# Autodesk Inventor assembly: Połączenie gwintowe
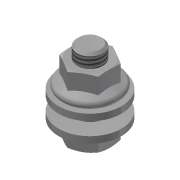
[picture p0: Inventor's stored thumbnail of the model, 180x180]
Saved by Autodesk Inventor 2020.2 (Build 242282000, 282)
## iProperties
Manager: www.cadconsulting.pl
Company: Fabian Stasiak CAD Consulting
ClientObjectVersion: 1
Created: 2011-01
Part Number: Połączenie gwintowe
Document SubType Name: Assembly
Designer: F.Stasiak
Author: F.Stasiak
Subject: Zbiór ćwiczeń. Autodesk Inventor 2020. Kurs podstawowy
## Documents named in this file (4)
- C:\2020_Kurs_podstawowy\R6 Zespoły\Kolizja\100-000\Design Accelerator\Połączenie gwintowe3.iam
- C:\2020_Kurs_podstawowy\Zasoby\Content Center Files\pl-PL\DIN 6796\DIN 6796 - 12.ipt
- C:\2020_Kurs_podstawowy\Zasoby\Content Center Files\pl-PL\DIN EN 24 017\ISO 4017 - M12 x 30DIN EN.ipt
- C:\2020_Kurs_podstawowy\Zasoby\Content Center Files\pl-PL\DIN 6923\DIN 6923 - M12 x 1,75.ipt
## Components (4 placed, 3 different names)
1. DIN 6796 12:1
2. DIN EN 24017 M12 x 30:1
3. DIN 6796 12:2
4. DIN 6923 M12:1
